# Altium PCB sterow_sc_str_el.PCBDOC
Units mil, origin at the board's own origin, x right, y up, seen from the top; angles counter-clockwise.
Board outline 6010 x 6345 mil, 2 copper layers (Top Layer, Bottom Layer); 70 components, 89 nets, 354 pads, 50 vias.
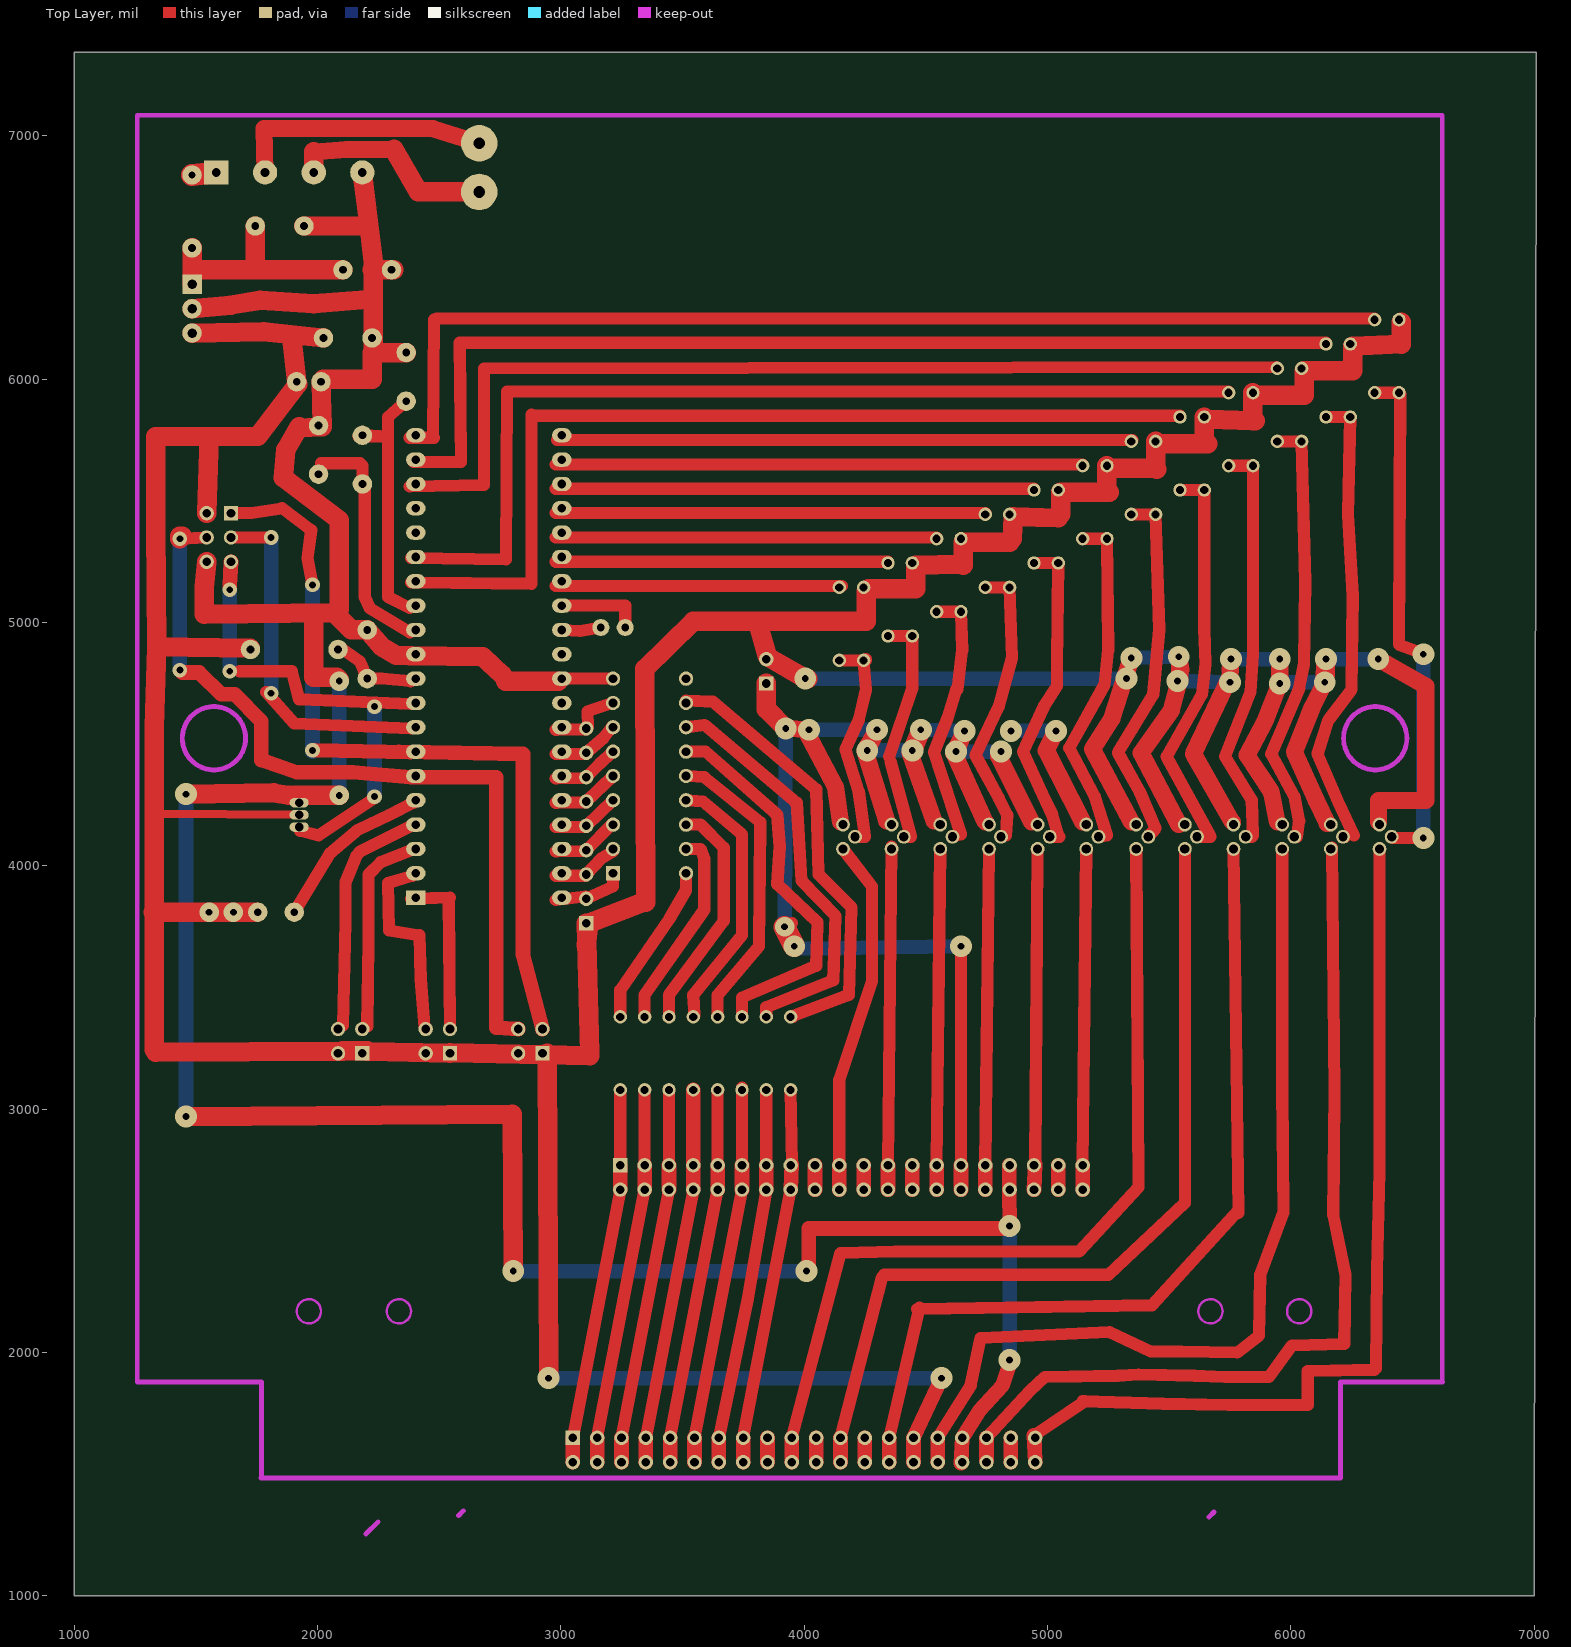
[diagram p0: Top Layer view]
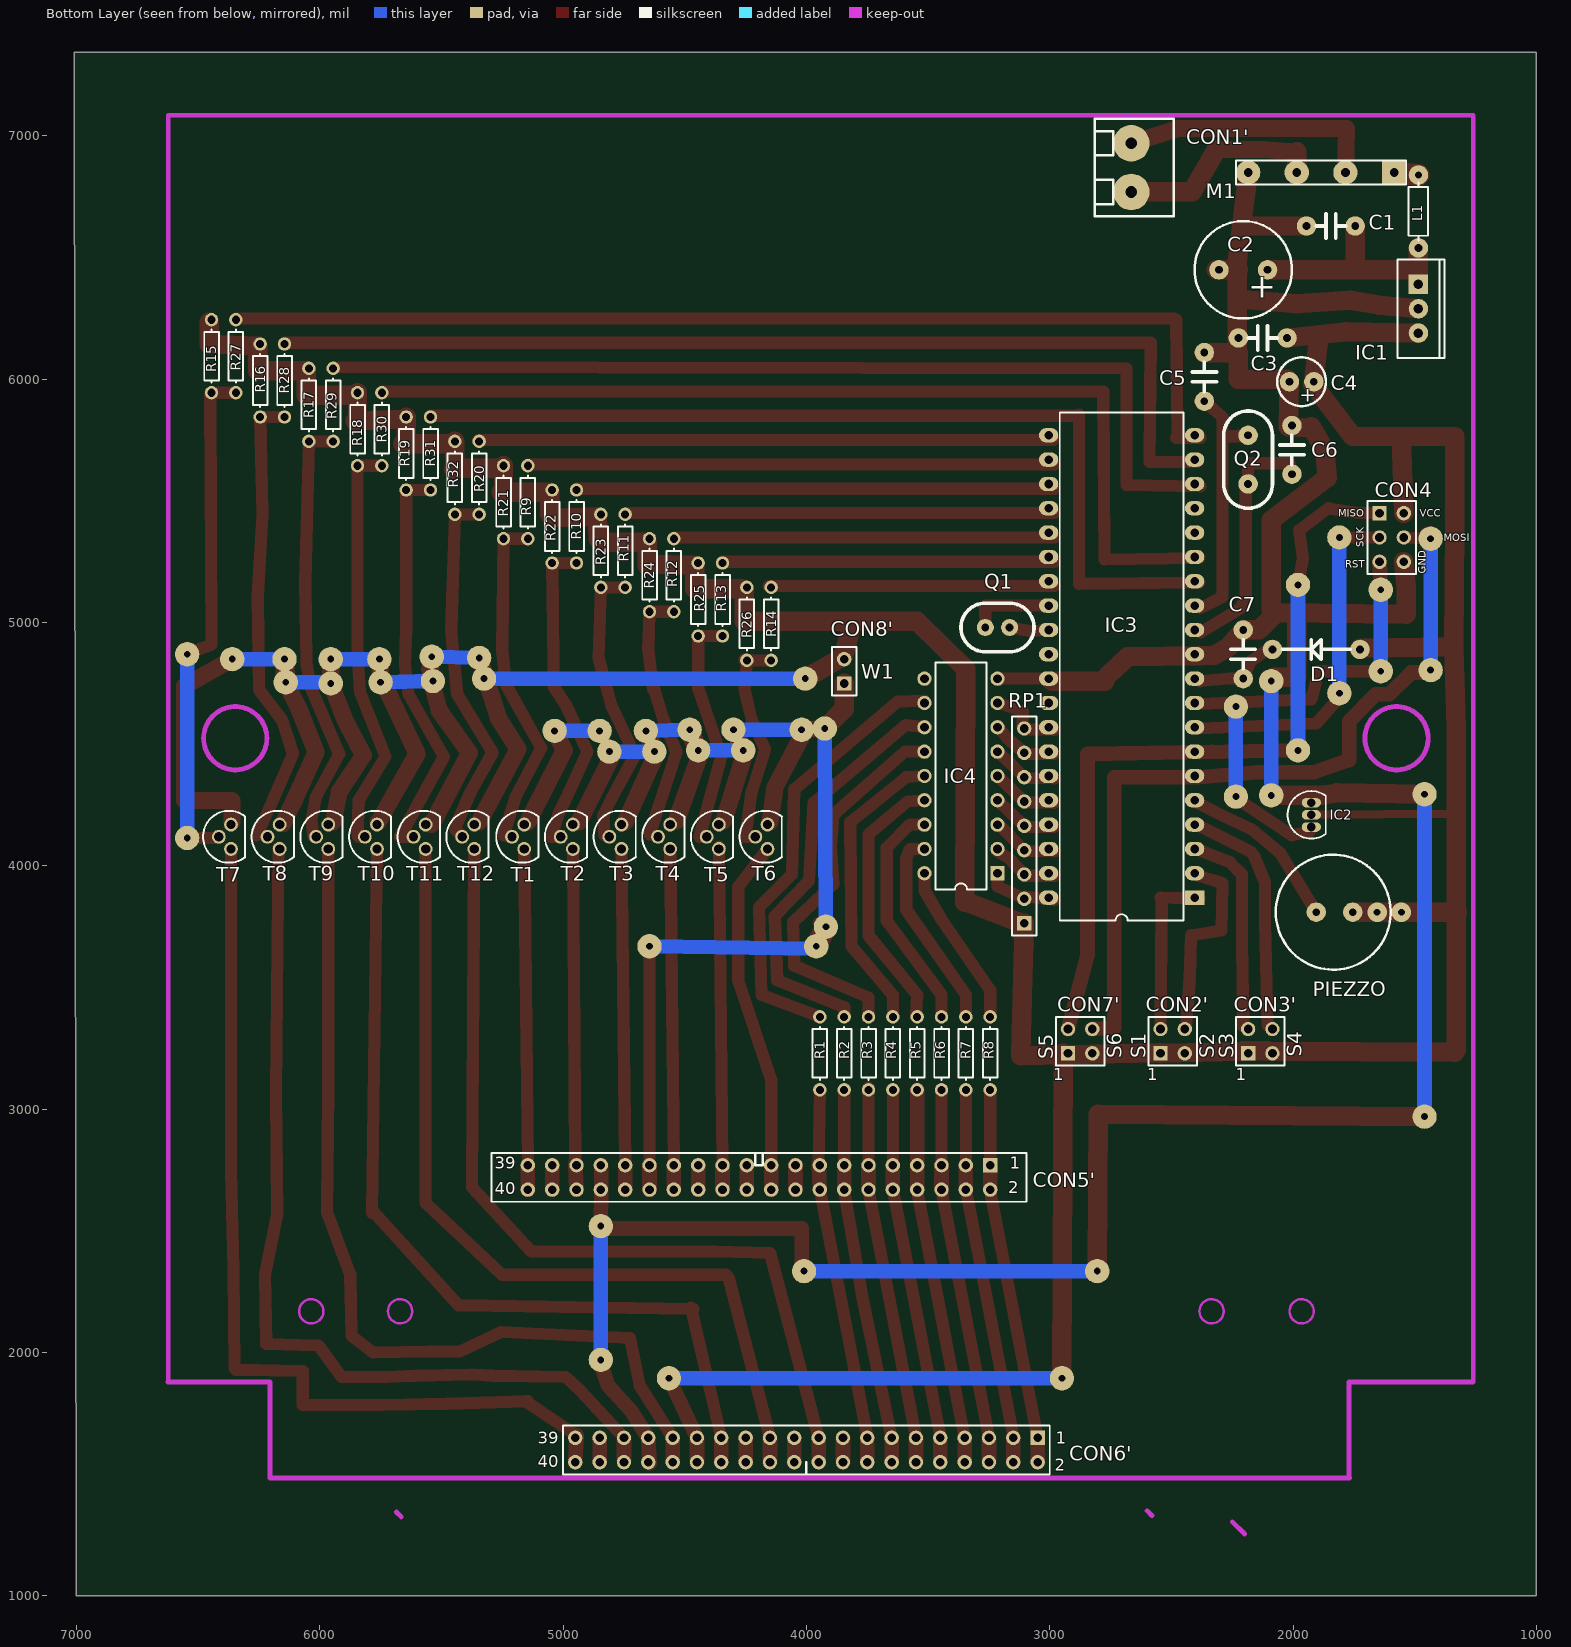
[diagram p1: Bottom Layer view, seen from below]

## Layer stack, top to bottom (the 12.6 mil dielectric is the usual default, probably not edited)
Top Layer: signal copper 1.4
Dielectric: dielectric 12.6, FR-4, Dk 4.8
Bottom Layer: signal copper 1.4

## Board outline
1000,1000 7000,1000 7010,7345 1000,7345

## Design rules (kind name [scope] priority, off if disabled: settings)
Clearance [All] p1: gap=10
ComponentClearance [All] p1: gap=1 collisioncheckmode=0
PolygonConnect [All] p1: connectstyle=Relief reliefconductorwidth=10 reliefentries=4 polygonreliefangle="90 Angle"
RoutingLayers [All] p1: top layer=Horizontal bottom layer=Vertical
RoutingVias [All] p1: holewidth=28 width=50 viastyle="Through Hole" minholewidth=28 minwidth=50 maxholewidth=28 maxwidth=50
SolderMaskExpansion [All] p1: expansion=4
TestPointUsage [All] p1: valid=0 allowmultiple=FALSE
Testpoint [All] p1: side=15 testpointundercomponent=TRUE minsize=40 maxsize=100 preferedsize=60 minholesize=0 maxholesize=40 preferedholesize=32 testpointgrid=1 style=1023 order=1234567890
Width [All] p1: maxlimit=90 minlimit=10 preferedwidth=10 toplayer_prefwidth=50 bottomlayer_prefwidth=80 minimp=50.000000 maximp=50.000000 favimp=50.000000
16 further rules are at their usual default settings.

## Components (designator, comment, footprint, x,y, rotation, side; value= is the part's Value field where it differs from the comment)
C1 "100nF" C2 1845,6630 r180 bottom
C2 "1000uF" CE10 2205,6450 r0 bottom
C3 "100nF" C2 2125,6170 r180 bottom
C4 "100uF" CE5 1965,5990 r0 bottom
C5 "27p" C2 2365,6010 r270 bottom
C6 "27p" C2 2005,5710 r270 bottom
C7 "100nF" C2 2205,4870 r270 bottom
CON1' "" ARK2 2665,6870 r90 bottom
CON2' "" HDR2X2 2545,3230 r180 bottom
CON3' "" HDR2X2 2185,3230 r180 bottom
CON4 "ISP" "HDR2X3_CEN - DUPLICATE" 1645,5450 r270 bottom
CON5' "Header 20X2" HDR2X20 3245,2770 r0 bottom
CON6' "Header 20X2" HDR2X20 3050,1650 r0 bottom
CON7' "" HDR2X2 2925,3230 r180 bottom
CON8' "Header 2" HDR1X2 3845,4750 r90 bottom
D1 "1N4148" D4 1905,4890 r0 bottom
IC1 "7805" 221A-04 1485,6290 r270 bottom
IC2 "DS1813" TO-92 1925,4210 r180 bottom
IC3 "ATmega8535" 40P6 2705,4820 r90 bottom
IC4 "ULN2803" DIP-18 3365,4370 r90 bottom
L1 "22uH" AXIAL-0.3#1 1485,6690 r90 bottom
M1 "Bridge1" HDR1X7 1585,6850 r0 bottom
PIEZZO "" PIEZO 1905,3810 r180 bottom (schematic designator Q3)
Q1 "32768Hz" X1 3265,4980 r0 bottom
Q2 "8MHz" X2 2185,5670 r90 bottom
R1 "Res2" AXIAL-0.3#2 3945,3230 r90 bottom
R2 "Res2" AXIAL-0.3#2 3845,3230 r90 bottom
R3 "Res2" AXIAL-0.3#2 3745,3230 r90 bottom
R4 "Res2" AXIAL-0.3#2 3645,3230 r90 bottom
R5 "Res2" AXIAL-0.3#2 3545,3230 r90 bottom
R6 "Res2" AXIAL-0.3#2 3445,3230 r90 bottom
R7 "Res2" AXIAL-0.3#2 3345,3230 r90 bottom
R8 "Res2" AXIAL-0.3#2 3245,3230 r90 bottom
R9 "Res2" AXIAL-0.3#2 5145,5495 r270 bottom
R10 "Res2" AXIAL-0.3#2 4945,5395 r270 bottom
R11 "Res2" AXIAL-0.3#2 4745,5295 r270 bottom
R12 "Res2" AXIAL-0.3#2 4545,5195 r270 bottom
R13 "Res2" AXIAL-0.3#2 4345,5095 r270 bottom
R14 "Res2" AXIAL-0.3#2 4145,4995 r270 bottom
R15 "3,3K" AXIAL-0.3#2 6445,6095 r90 bottom
R16 "3,3K" AXIAL-0.3#2 6245,5995 r90 bottom
R17 "3,3K" AXIAL-0.3#2 6045,5895 r90 bottom
R18 "3,3K" AXIAL-0.3#2 5845,5795 r90 bottom
R19 "3,3K" AXIAL-0.3#3 5645,5695 r90 bottom
R20 "3,3k" AXIAL-0.3#2 5345,5595 r270 bottom
R21 "Res2" AXIAL-0.3#2 5245,5495 r90 bottom
R22 "Res2" AXIAL-0.3#2 5045,5395 r90 bottom
R23 "Res2" AXIAL-0.3#2 4845,5295 r90 bottom
R24 "Res2" AXIAL-0.3#2 4645,5195 r90 bottom
R25 "Res2" AXIAL-0.3#2 4445,5095 r90 bottom
R26 "Res2" AXIAL-0.3#2 4245,4995 r90 bottom
R27 "3,3K" AXIAL-0.3#2 6345,6095 r270 bottom
R28 "3,3K" AXIAL-0.3#2 6145,5995 r270 bottom
R29 "3,3K" AXIAL-0.3#2 5945,5895 r270 bottom
R30 "3,3K" AXIAL-0.3#2 5745,5795 r270 bottom
R31 "3,3K" AXIAL-0.3#2 5545,5695 r270 bottom
R32 "3,3K" AXIAL-0.3#2 5445,5595 r90 bottom
RP1 "8x10K" HDR1X9 3105,3765 r90 bottom
T1 "BC557" TO92 5160,4070 r0 bottom
T2 "BC557" TO92 4960,4070 r0 bottom
T3 "*" TO92 4760,4070 r0 bottom
T4 "BC557" TO92 4560,4070 r0 bottom
T5 "BC557" TO92 4360,4070 r0 bottom
T6 "BC557" TO92 4160,4070 r0 bottom
T7 "BC557" TO92 6365,4070 r0 bottom
T8 "BC557" TO92 6165,4070 r0 bottom
T9 "BC557" TO92 5965,4070 r0 bottom
T10 "BC557" TO92 5765,4070 r0 bottom
T11 "BC557" TO92 5565,4070 r0 bottom
T12 "BC557" TO92 5365,4070 r0 bottom

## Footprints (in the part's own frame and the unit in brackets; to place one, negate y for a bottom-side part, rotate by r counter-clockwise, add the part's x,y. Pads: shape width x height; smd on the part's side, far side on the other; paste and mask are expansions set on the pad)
40P6 [mm]
  rect 1.5x2.032 hole 0.9: 1(-24.13,-7.62)
  oval 1.5x2.032 hole 0.9: 2(-21.59,-7.62) 3(-19.05,-7.62) 4(-16.51,-7.62) 5(-13.97,-7.62) 6(-11.43,-7.62) 7(-8.89,-7.62) 8(-6.35,-7.62) 9(-3.81,-7.62) 10(-1.27,-7.62) 11(1.27,-7.62) 12(3.81,-7.62) 13(6.35,-7.62) 14(8.89,-7.62) 15(11.43,-7.62) 16(13.97,-7.62) 17(16.51,-7.62) 18(19.05,-7.62) 19(21.59,-7.62) 20(24.13,-7.62) 21(24.13,7.62) 22(21.59,7.62) 23(19.05,7.62) 24(16.51,7.62) 25(13.97,7.62) 26(11.43,7.62) 27(8.89,7.62) 28(6.35,7.62) 29(3.81,7.62) 30(1.27,7.62) 31(-1.27,7.62) 32(-3.81,7.62) 33(-6.35,7.62) 34(-8.89,7.62) 35(-11.43,7.62) 36(-13.97,7.62) 37(-16.51,7.62) 38(-19.05,7.62) 39(-21.59,7.62) 40(-24.13,7.62)
  silkscreen extent -26.5,-6.45 26.5,6.45
221A-04 [mil]
  rect 80x80 hole 39.37: 1(-100,0)
  round 80 hole 39.37: 2(0,0) 3(100,0)
  silkscreen extent -203,-87 203,106
ARK2 [mil]
  round 150 hole 48: 1(-100,0) 2(100,0)
  silkscreen extent -200,-175 200,150
AXIAL-0.3#1 [mil]
  round 80 hole 33.47: 1(-150,0)
  round 80 hole 28: 2(150,0)
  silkscreen extent -120,-40 120,40
AXIAL-0.3#2 [mil]
  round 55.12 hole 33.46: 1(-150,0) 2(150,0)
  silkscreen extent -109,-30 109,30
AXIAL-0.3#3 [mil]
  round 55.12 hole 33.46: 1(-150,0)
  round 55.12 hole 33.47: 2(150,0)
  silkscreen extent -109,-30 109,30
C2 [mil]
  round 80 hole 32: 1(-100,0) 2(100,0)
  silkscreen extent -60,-50 60,50
CE5 [mil]
  round 80 hole 32: 1(-50,0) 2(50,0)
  silkscreen extent -100,-100 100,100
CE10 [mil]
  round 80 hole 32: 1(-100,0) 2(100,0)
  silkscreen extent -200,-200 200,200
D4 [mil]
  round 80 hole 32: 1(-180,0) 2(180,0)
  silkscreen extent -140,-40 140,40
DIP-18 [mm]
  rect 1.5x1.5 hole 0.9: 1(-10.16,-3.81)
  round 1.5 hole 0.9: 2(-7.62,-3.81) 3(-5.08,-3.81) 4(-2.54,-3.81) 5(0,-3.81) 6(2.54,-3.81) 7(5.08,-3.81) 8(7.62,-3.81) 9(10.16,-3.81) 10(10.16,3.81) 11(7.62,3.81) 12(5.08,3.81) 13(2.54,3.81) 14(0,3.81) 15(-2.54,3.81) 16(-5.08,3.81) 17(-7.62,3.81) 18(-10.16,3.81)
  silkscreen extent -11.85,-2.65 11.85,2.65
HDR1X2 [mm]
  rect 1.5x1.5 hole 0.9: 1(0,0)
  round 1.5 hole 0.9: 2(2.54,0)
  silkscreen extent -1.27,-1.27 3.81,1.27
HDR1X7 [mm]
  rect 2.54x2.54 hole 0.9: 1(0,0)
  round 2.54 hole 0.9: 2(5.08,0) 3(10.16,0) 4(15.24,0)
  silkscreen extent -1.27,-1.27 16.51,1.27
HDR1X9 [mm]
  rect 1.5x1.5 hole 0.9: 1(0,0)
  round 1.5 hole 0.9: 2(2.54,0) 3(5.08,0) 4(7.62,0) 5(10.16,0) 6(12.7,0) 7(15.24,0) 8(17.78,0) 9(20.32,0)
  silkscreen extent -1.27,-1.27 21.59,1.27
HDR2X2 [mm]
  rect 1.5x1.5 hole 0.9: 1(0,0)
  round 1.5 hole 0.9: 2(0,2.54) 3(2.54,0) 4(2.54,2.54)
  silkscreen extent -1.27,-1.27 3.81,3.81
"HDR2X3_CEN - DUPLICATE" [mm]
  rect 1.5x1.5 hole 0.9: 1(0,0)
  round 1.5 hole 0.9: 2(2.54,0) 3(5.08,0) 4(5.08,2.54) 5(2.54,2.54) 6(0,2.54)
  silkscreen extent -1.27,-1.27 6.35,3.81
HDR2X20 [mm]
  rect 1.5x1.5 hole 0.9: 1(0,0)
  round 1.5 hole 0.9: 2(0,2.54) 3(2.54,0) 4(2.54,2.54) 5(5.08,0) 6(5.08,2.54) 7(7.62,0) 8(7.62,2.54) 9(10.16,0) 10(10.16,2.54) 11(12.7,0) 12(12.7,2.54) 13(15.24,0) 14(15.24,2.54) 15(17.78,0) 16(17.78,2.54) 17(20.32,0) 18(20.32,2.54) 19(22.86,0) 20(22.86,2.54) 21(25.4,0) 22(25.4,2.54) 23(27.94,0) 24(27.94,2.54) 25(30.48,0) 26(30.48,2.54) 27(33.02,0) 28(33.02,2.54) 29(35.56,0) 30(35.56,2.54) 31(38.1,0) 32(38.1,2.54) 33(40.64,0) 34(40.64,2.54) 35(43.18,0) 36(43.18,2.54) 37(45.72,0) 38(45.72,2.54) 39(48.26,0) 40(48.26,2.54)
  silkscreen extent -3.81,-1.27 52.07,3.81
PIEZO [mil]
  round 80 hole 32: 1(0,0) 2(150,0)
  silkscreen extent -166,-236 306,236
TO92 [mil]
  round 57 hole 38: 1(0,0) 2(50,-50) 3(0,-100)
  silkscreen extent -59,-157 115,57
TO-92 [mm]
  oval 2x1 hole 0.9: 1(0,-1.27) 2(0,0) 3(0,1.27)
  silkscreen extent -2.48,-2.48 1.5,2.48
X1 [mil]
  round 70 hole 32: 1(0,0) 2(-100,0)
  silkscreen extent -200,-100 100,100
X2 [mil]
  round 80 hole 32: 1(100,0) 2(-100,0)
  silkscreen extent -200,-100 200,100

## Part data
C1 C3 C5 C6 C7: library part C, "Kondensator"
C2 C4: library part EL, "Elektrolit"
CON1': library part "Header 2", "Header, 2-Pin"
CON2' CON3' CON7': library part "Header 2X2", "Header, 2-Pin, Dual row"
CON4: library part "Header 3X2_ISP", "Header, 3-Pin, Dual row"
CON5': "Header, 20-Pin, Dual row"
CON6': library part "Edge Con 22", "22-Pin Edge Connector"
CON8': "Header, 2-Pin"
D1: library part D, "Dioda"
IC1: library part MC7805ACT, "3-Terminal Positive Fixed Voltage Regulator"
IC2: library part DS1813-10, "5V EconoReset with Pushbutton"
IC3: library part ATmega8535-16PU, "8-Bit AVR Microcontroller with 8K Bytes of In-System Programmable Flash Memory"
IC4: library part ULN2803A, "Octal Peripheral Driver Array"
M1: "Full Wave Diode Bridge"
PIEZZO: library part PIEZO, "Loudspeaker"
Q1 Q2: library part CRYSTAL_1, "rezonator"
R1 R2 R3 R4 R5 R6 R7 R8 R9 R10 R11 R12 R13 R14 R21 R22 R23 R24 R25 R26: "Resistor"
R15 R16 R17 R18 R19 R20 R27 R28 R29 R30 R31 R32: library part Res2, "Resistor"
RP1: library part "Res Pack4", "Resistor Array"
T1 T2 T4 T5 T6 T7 T8 T9 T10 T11 T12: "Amplifier Transistor PNP Silicon"
T3: library part BC557, "Amplifier Transistor PNP Silicon"

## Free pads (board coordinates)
  round 30 on Keep-Out: 0(2885,1335)
  round 100 smd far side: 0(6545,4115) 1(6545,4870) 3(1980,5155) 4(1980,4475) 4(2805,2335) 4(3925,4565) 4(4020,4560) 4(4645,3670) 5(2235,4655) 5(3960,3670) 6(2235,4285) 7(2090,4760) 8(2090,4290) 9(2950,1895) 9(4845,2520) 10(3920,3750) 10(6360,4850) 11(6145,4850) 12(6140,4755) 13(5955,4750) 14(5955,4850) 15(4565,1895) 15(5750,4755) 16(4845,1970) 16(5755,4850) 17(5535,4760) 18(5540,4860) 19(5325,4770) 20(5345,4855) 21(4005,4770) 22(4810,4470) 23(4625,4470) 24(4445,4475) 25(4480,4560) 26(4660,4555) 27(1640,4800) 27(4850,4555) 28(1640,5135) 28(5035,4555) 29(1810,4710) 29(4260,4475) 30(1810,5350) 30(4300,4560) 31(1435,5345) 32(1435,4805) 35(1460,4295) 36(1460,4295) 37(1460,2970) 38(1460,2970) 41(4010,2335)

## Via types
v1: diameter 90, hole 28, Top Layer to Bottom Layer, 35 vias
v2: diameter 60, hole 28, Top Layer to Bottom Layer, 10 vias
v3: diameter 80, hole 28, Top Layer to Bottom Layer, 5 vias

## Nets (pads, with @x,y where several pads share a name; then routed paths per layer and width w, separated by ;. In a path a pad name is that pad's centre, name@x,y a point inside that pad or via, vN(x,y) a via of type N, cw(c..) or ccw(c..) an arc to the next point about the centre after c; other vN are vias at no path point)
A1': CON5'.39 CON5'.40 T1.1 | length 1400.1
  Top Layer w50: CON5'.39 T1.1
  Top Layer w60: CON5'.40 CON5'.39
A2': CON5'.35 CON5'.36 T2.1 | length 1400.2
  Top Layer w50: CON5'.35@4950,2775 T2.1
  Top Layer w60: CON5'.36 CON5'.35@4950,2775
A3': CON5'.31 CON5'.32 T3.1 | length 1400.1
  Top Layer w50: CON5'.31 T3.1
  Top Layer w60: CON5'.32 CON5'.31
A4': CON5'.27 CON5'.28 T4.1 | length 1400.1
  Top Layer w50: CON5'.27 T4.1
  Top Layer w60: CON5'.28 CON5'.27
A5': CON5'.23 CON5'.24 T5.1 | length 1410.1
  Top Layer w50: CON5'.23 T5.1@4360,4080
  Top Layer w60: CON5'.24 CON5'.23
A6': CON5'.19 CON5'.20 T6.1 | length 1462.7
  Top Layer w50: CON5'.19 4145,3120 4280,3530 4280,3915 T6.1
  Top Layer w60: CON5'.20 CON5'.19
A7': CON6'.39 CON6'.40 T7.1 | length 3837.9
  Top Layer w50: CON6'.39@4945,1660 5155,1800 ; 5145,1800 5475,1790 5745,1785 6070,1785 6070,1925 6345,1930 ; 6350,1935 6355,2340 6365,2745 6365,3535 T7.1
  Top Layer w60: CON6'.39@4945,1660 CON6'.40
A8': CON6'.35 CON6'.36 T8.1 | length 3778.4
  Top Layer w50: CON6'.35 4930,1845 4990,1900 5290,1905 5375,1910 5605,1905 5730,1900 5910,1900 6005,2030 6220,2035 6225,2320 6175,2565 6180,3070 T8.1@6170,4075
  Top Layer w60: CON6'.36@4750,1560 CON6'.35
A9': CON6'.31 CON6'.32 T9.1 | length 3757.7
  Top Layer w50: CON6'.31 4685,1865 4725,2060 5255,2085 5425,2005 5550,2005 5780,2000 5870,2070 5875,2320 5970,2575 5965,3080 T9.1
  Top Layer w60: CON6'.32 CON6'.31
A10': CON6'.27 CON6'.28 T10.1 | length 3637
  Top Layer w50: CON6'.27 4475,2185 ; 4465,2180 5430,2195 5785,2585 ; T10.1 5785,2575
  Top Layer w60: CON6'.28 CON6'.27
A11': CON6'.23 CON6'.24 T11.1 | length 3568.1
  Top Layer w50: CON6'.23 4320,2310 ; 4330,2320 5250,2320 5565,2615 ; 5565,2620 T11.1@5565,4055
  Top Layer w60: CON6'.24 CON6'.23
A12': CON6'.19 CON6'.20 T12.1 | length 3611.9
  Top Layer w50: CON6'.19 4150,2410 4375,2415 5130,2415 5375,2680 ; T12.1 5375,2685
  Top Layer w60: CON6'.20 CON6'.19
A': CON5'.15 CON5'.16 CON6'.15 CON6'.16 R1.1 | length 1548.6
  Top Layer w50: CON6'.15 CON5'.16 ; R1.1 CON5'.15@3950,2775
  Top Layer w60: CON6'.16 CON6'.15 ; CON5'.16 CON5'.15@3950,2775
B': CON5'.13 CON5'.14 CON6'.13 CON6'.14 R2.1 | length 1548.7
  Top Layer w50: CON6'.13 3770,2225 CON5'.14 ; CON5'.13 R2.1
  Top Layer w60: CON6'.14 CON6'.13 ; CON5'.14 CON5'.13
C1: IC3.22 R9.1 | length 2165
  Top Layer w50: IC3.22@2980,5650 R9.1@5145,5650
C2: IC3.23 R10.1 | length 1965
  Top Layer w50: IC3.23@2980,5550 R10.1@4945,5550
C3: IC3.24 R11.1 | length 1765
  Top Layer w50: IC3.24@2980,5450 R11.1@4745,5450
C4: IC3.25 R12.1 | length 1565
  Top Layer w50: IC3.25@2980,5350 R12.1@4545,5350
C5: IC3.26 R13.1 | length 1365
  Top Layer w50: IC3.26@2980,5250 R13.1@4345,5250
C6: IC3.27 R14.1 | length 1175
  Top Layer w50: IC3.27@2980,5150 R14.1@4155,5150
C7: IC3.20 R27.1 | length 4440
  Top Layer w50: IC3.20@2380,5760 2480,5760 ; 2475,5760 2480,6245 ; 2490,6250 R27.1@6345,6250
C8: IC3.19 R28.1 | length 4235
  Top Layer w50: IC3.19@2395,5660 2580,5660 ; 2590,5660 2585,6150 R28.1@6145,6150
C9: IC3.18 R29.1 | length 4047.1
  Top Layer w50: IC3.18@2380,5560 2685,5565 2685,6045 5940,6050 R29.1
C10: IC3.15 R30.1 | length 4045.1
  Top Layer w50: IC3.15@2385,5265 2775,5260 2780,5950 R30.1@5745,5950
C11: IC3.14 R31.1 | length 3855
  Top Layer w50: IC3.14@2385,5165 2880,5160 2880,5855 ; 2880,5850 R31.1@5545,5850
C12: IC3.21 R20.1 | length 2365
  Top Layer w50: IC3.21@2985,5750 R20.1@5350,5750
C': CON5'.11 CON5'.12 CON6'.11 CON6'.12 R3.1 | length 1558.5
  Top Layer w50: CON6'.11 CON5'.12 ; CON5'.11 R3.1@3745,3090
  Top Layer w60: CON6'.12 CON6'.11 ; CON5'.12 CON5'.11
D': CON5'.9 CON5'.10 CON6'.9 CON6'.10 R4.1 | length 1548.5
  Top Layer w50: CON6'.9 CON5'.10 ; CON5'.9 R4.1
  Top Layer w60: CON6'.10 CON6'.9 ; CON5'.10 CON5'.9
DP': CON5'.1 CON5'.2 CON6'.1 CON6'.2 R8.1 | length 1548.5
  Top Layer w50: CON6'.1 CON5'.2 ; CON5'.1 R8.1
  Top Layer w60: CON6'.2 CON6'.1 ; CON5'.2 CON5'.1
E': CON5'.7 CON5'.8 CON6'.7 CON6'.8 R5.1 | length 1548.5
  Top Layer w50: CON6'.7 CON5'.8
  Top Layer w60: CON6'.8 CON6'.7 ; CON5'.8 R5.1
F': CON5'.5 CON5'.6 CON6'.5 CON6'.6 R6.1 | length 1548.5
  Top Layer w50: CON6'.5 CON5'.6 ; CON5'.5 R6.1
  Top Layer w60: CON6'.6 CON6'.5 ; CON5'.6 CON5'.5
G': CON5'.3 CON5'.4 CON6'.3 CON6'.4 R7.1 | length 1548.5
  Top Layer w50: CON6'.3 CON5'.4 ; CON5'.3 R7.1
  Top Layer w60: CON6'.4 CON6'.3 ; CON5'.4 CON5'.3
GND': C1.1 C2.2 C3.1 C4.2 C5.1 C6.1 C7.1 CON4.4 CON5'.33 CON5'.34 CON6'.33 CON6'.34 IC1.2 IC2.3 IC3.11 IC3.31 IC4.9 M1.4 pad.4@2805,2335 pad.7 pad.8 pad.9@4845,2520 pad.16@4845,1970 pad.35 pad.36 pad.37 pad.38 pad.41 | length 13655.8
  Top Layer w50: C4.2 C4.2@2025,6000 ; IC3.31@2990,4770 IC4.9
  Top Layer w60: v1@4020,2340 4020,2510 v1@4845,2510 ; CON6'.34@4645,1545 CON6'.33 4720,1760 4815,1865 v1@4850,1970 ; CON5'.33@4842.83,2769.98 4843.7,2669.99 v1(4845,2520)
  Top Layer w80: v1(1460,2970) 2800,2980 v1@2805,2345 ; v1(1460,4295) 1820,4300 1885,4290 ; IC1.2 1645,6305 1765,6325 1985,6310 2230,6330 ; CON4.4 1535,5145 1535,5035 2070,5040 2140,4970 C7.1 2265,4900 2325,4865 IC3.11@2380.06,4864.22 ; 1905,4290 v3(2090,4290) ; 1925,5805 1870,5710 1860,5595 2090,5420 2090,5055 ; 1930,5800 2020,5805 2019.85,5810.4 C4.2 ; C1.1 2212.12,6630 ; 1985,5005 1985,4775 2080,4775 v3@2090,4765 ; C4.2@2025,6000 2225,6000 2225,6110 C5.1 ; M1.4 2212.12,6630 ; 2225,6450 C2.2@2315,6450 ; 2230,6105 2230,6485 2212.12,6630 ; IC3.11@2384.99,4864.16 2680,4860 2760,4785 ; 2775,4760 IC3.31@2990,4760
  Bottom Layer w60: v1(1460,2970) v1(1460,4295) ; v3(2090,4290) v3(2090,4760) ; v1(2805,2335) v1(4010,2335) ; v1(4845,1970) v1(4845,2520)
MISO: CON4.1 CON7'.2 IC3.7 pad.3 pad.4@1980,4475 | length 3325
  Top Layer w50: CON4.1 1730,5450 1855,5470 1975,5380 1960,5265 v2(1980,5155) ; IC3.7@2381.23,4466.62 2385.17,4465.9 IC3.7@2390,4465
  Top Layer w60: v2@1990,4475 IC3.7@2381.23,4466.62 ; 2335,4470 2845,4460 2845,3635 CON7'.2
  Bottom Layer w60: pad.4@1980,4470 v2(1980,5155)
  other v2: 1980,4475
MOSI: CON4.5 CON7'.4 IC3.6 pad.31 pad.32 | length 3336.4
  Top Layer w50: v2(1435,5345) CON4.5
  Top Layer w60: v2@1445,4795 1515,4795 1605,4705 1660,4705 1770,4595 1770,4435 1915,4385 2145,4385 2385,4365 2735,4365 2735,3855 2735,3335 CON7'.4
  Top Layer w80: v2(1435,5345) 1445,5355 v2@1435,5355
  Bottom Layer w60: v2(1435,4805) v2(1435,5345)
NC1': CON5'.37 CON5'.38 | length 100
  Top Layer w60: CON5'.38 CON5'.37
NC2': CON5'.25 CON5'.26 | length 100
  Top Layer w60: CON5'.26 CON5'.25
NC3': CON5'.21 CON5'.22 | length 100
  Top Layer w60: CON5'.22 CON5'.21
NC4': CON5'.17 CON5'.18 | length 100
  Top Layer w60: CON5'.18 CON5'.17
NC5': CON6'.37 CON6'.38 | length 100
  Top Layer w60: CON6'.38 CON6'.37
NC6': CON6'.25 CON6'.26 | length 100
  Top Layer w60: CON6'.26 CON6'.25
NC7': CON6'.21 CON6'.22 | length 100
  Top Layer w60: CON6'.22 CON6'.21
NC8': CON6'.17 CON6'.18 | length 100
  Top Layer w60: CON6'.18 CON6'.17
NetC1_2: C1.2 C2.1 IC1.1 L1.1 | length 945
  Top Layer w80: IC1.1 L1.1 ; 1485,6450 C2.1 ; 1745,6455 C1.2
NetCON1'_1: CON1'.1 M1.3 | length 866.9
  Top Layer w70: 1985,6935 2120,6945 2315,6945
  Top Layer w80: M1.3 1985,6935 ; 2315,6945 2415,6770 CON1'.1
NetCON1'_2: CON1'.2 M1.2 | length 1074.3
  Top Layer w70: M1.2 1780,7030 2475,7030 CON1'.2
NetIC4_11: IC4.11 R1.2 | length 1844.6
  Top Layer w50: IC4.11@3515,4680 3625,4675 4050,4315 4060,3965 4195,3830 4185,3470 R1.2 ; R1.2 3955,3380 R1.2
NetIC4_12: IC4.12 R2.2 | length 1696
  Top Layer w50: IC4.12 3590,4580 3970,4260 3990,3940 4130,3795 4120,3530 3845,3420 R2.2
NetIC4_13: IC4.13 R3.2 | length 1576.9
  Top Layer w50: IC4.13 3595,4470 3890,4210 3900,4080 3890,3925 4055,3770 4050,3590 3745,3460 R3.2
NetIC4_14: IC4.14 R4.2 | length 1207.9
  Top Layer w50: IC4.14@3525,4370 3590,4365 3820,4180 ; R4.2 3645,3470 3815,3670 3820,4165
NetIC4_15: IC4.15 R5.2 | length 1103
  Top Layer w50: IC4.15 3585,4265 3745,4130 3745,3715 3545,3470 3550,3385 R5.2
NetIC4_16: IC4.16 R6.2 | length 963.4
  Top Layer w50: R6.2 3445,3470 3670,3775 3670,4075 3575,4170 IC4.16
NetIC4_17: IC4.17 R7.2 | length 809.9
  Top Layer w50: R7.2@3345,3390 3345,3470 3590,3820 3590,4030 3575,4070 IC4.17@3525,4070
NetIC4_18: IC4.18 R8.2 | length 671.2
  Top Layer w50: R8.2 3245,3490 3445,3780 3515,3900 IC4.18
NetL1_2: L1.2 M1.1 | length 100.5
  Top Layer w90: L1.2 M1.1
NetR9_2: R9.2 R21.1 T1.2 | length 1427.4
  Top Layer w50: R9.2 R21.1 5250,4885 5235,4745 5090,4485 5195,4285 5245,4125 T1.2
NetR10_2: R10.2 R22.1 T2.2 | length 1324.8
  Top Layer w50: R10.2 R22.1 5040,4830 5040,4740 4985,4655 4900,4470 4980,4295 5020,4210 5045,4125 ; T2.2 5050,4120
NetR11_2: R11.2 R23.1 T3.2 | length 1181.5
  Top Layer w50: R11.2 R23.1 4855,4855 4800,4655 4705,4455 4800,4280 4835,4210 T3.2@4830,4125
NetR12_2: R12.2 R24.1 T4.2 | length 1080.9
  Top Layer w50: 4535,4465 4645,4130 T4.2 ; 4535,4470 4590,4610 4625,4725 ; R12.2 R24.1 4650,4885 4630,4725
NetR13_2: R13.2 R25.1 T5.2 | length 962.1
  Top Layer w50: R13.2 R25.1 4445,4730 4350,4450 ; 4355,4430 4440,4120 T5.2
NetR14_2: R14.2 R26.1 T6.2 | length 876.3
  Top Layer w50: R14.2@4165,4845 R26.1 4255,4725 4225,4600 4170,4480 4225,4305 4250,4120.28 4250,4120 T6.2 ; R26.1@4254.91,4844.82 R26.1@4255,4850
NetR15_1: pad.0@6545,4115 pad.1 R15.1 R27.2 T7.2 | length 2132.5
  Top Layer w50: R27.2 R15.1 6450,5940 6445,4910 6540,4875 v1(6545,4870) ; T7.2 6420,4115 v1(6545,4115)
  Bottom Layer w60: v1(6545,4115) v1(6545,4870)
NetR16_1: R16.1 R28.2 T8.2 | length 1899
  Top Layer w50: R28.2 R16.1 6235,5445 6255,5110 6250,4725 6155,4600 6110,4460 6195,4265 6260,4125 ; T8.2 T8.2@6222.08,4120
NetR17_1: R17.1 R29.2 T9.2 | length 1787.6
  Top Layer w50: R29.2 R17.1 6060,5165 6055,4830 6035,4730 5920,4460 6015,4285 6035,4185 6025,4120 T9.2
NetR18_1: R18.1 R30.2 T10.2 | length 1703.5
  Top Layer w50: R30.2 R18.1 5845,4975 5845,4870 5835,4715 5730,4450 5840,4270 5845,4125 5840,4120 T10.2
NetR19_1: R19.1 R31.2 T11.2 | length 1665.2
  Top Layer w50: R31.2 R19.1 5645,4975 5650,4830 5635,4705 5490,4450 5670,4120 T11.2
NetR20_2: R20.2 R32.1 T12.2 | length 1515
  Top Layer w50: R20.2 R32.1 5460,4970 5435,4705 5290,4465 5380,4305 5445,4155 T12.2
OSC1: IC3.28 Q1.1 | length 350
  Top Layer w50: IC3.28 3265,5070 Q1.1
OSC2: IC3.29 Q1.2 | length 161.5
  Top Layer w50: IC3.29 3080,4965 Q1.2
PA0: IC3.40 IC4.1 RP1.2 | length 301.4
  Top Layer w50: IC3.40@2980,3860 3100,3875 3115,3870 3215,3915 IC4.1
PA1: IC3.39 IC4.2 RP1.3 | length 283.8
  Top Layer w50: IC3.39@2980,3960 3100,3960 RP1.3 3165,4030 3215,4060 IC4.2
PA2: IC3.38 IC4.3 RP1.4 | length 278.5
  Top Layer w50: IC3.38@2980,4060 2985.05,4060.05 RP1.4@3105.04,4061.34 ; RP1.4 3210,4170 IC4.3
PA3: IC3.37 IC4.4 RP1.5 | length 277.1
  Top Layer w50: IC3.37@2980,4160 2985.04,4160.04 RP1.5@3105.03,4161.11 ; RP1.5 IC4.4
PA4: IC3.36 IC4.5 RP1.6 | length 277.1
  Top Layer w50: IC3.36@2980,4260 2985.04,4260.04 RP1.6@3105.03,4260.94 ; RP1.6 IC4.5
PA5: IC3.35 IC4.6 RP1.7 | length 277.2
  Top Layer w50: IC3.35@2980,4360 2985.06,4360.07 RP1.7@3105.04,4361.63 ; RP1.7 3160,4420 IC4.6
PA6: IC3.34 IC4.7 RP1.8 | length 274.2
  Top Layer w50: IC3.34@2980,4460 2985.03,4460.03 RP1.8@3105.02,4460.72 ; RP1.8 3175,4525 IC4.7@3210,4570
PA7: IC3.33 IC4.8 RP1.9 | length 298.5
  Top Layer w50: IC3.33@2980,4560 2985.03,4560.03 RP1.9@3105.02,4560.65 ; RP1.9@3112.24,4572.24 3110,4635 IC4.8
PIEZO: IC3.5 PIEZZO.1 | length 687.1
  Top Layer w50: PIEZZO.1 2050,4050 2170,4150 2295,4210 IC3.5@2395,4260
RST: CON4.3 IC2.1 IC3.9 pad.5@2235,4655 pad.6 pad.27@1640,4800 pad.28@1640,5135 | length 1954.4
  Top Layer w50: 1680,4800 1895,4800 1925,4685 IC3.9@2385,4665 ; IC2.1@1930,4145 2005,4125 v2@2235,4280
  Top Layer w60: v2@1640,5150 CON4.3
  Bottom Layer w60: v2(1640,4800) v2(1640,5135) ; v2(2235,4285) v2(2235,4655)
S1': CON2'.2 IC3.1 | length 702.2
  Top Layer w50: IC3.1@2385,3865 2545,3870 2540,3865 CON2'.2
S2': CON2'.4 IC3.2 | length 801.7
  Top Layer w50: IC3.2@2390,3960 2290,3930 2295,3735 2420,3715 2425,3535 CON2'.4@2440,3340
S3': CON3'.2 IC3.3 | length 830.4
  Top Layer w50: CON3'.2@2205,3340 2210,3690 2210,3965 2260,4015 IC3.3@2385,4065
S4': CON3'.4 IC3.4 | length 963.8
  Top Layer w50: CON3'.4@2105,3345 2115,3770 2115,3930 2160,4040 2175,4060 IC3.4@2385,4165
SCK: CON4.2 IC3.8 pad.29@1810,4710 pad.30@1810,5350 | length 1444
  Top Layer w50: CON4.2@1660,5350 v2(1810,5350) ; v2@1790,4715 1905,4585 IC3.8@2385,4565
  Bottom Layer w60: v2(1810,4710) v2(1810,5350)
VCC: CON5'.29 CON5'.30 CON8'.1 pad.4@3925,4565 pad.4@4020,4560 pad.4@4645,3670 pad.5@3960,3670 pad.10@3920,3750 pad.22 pad.23 pad.24 pad.25 pad.26 pad.27@4850,4555 pad.28@5035,4555 pad.29@4260,4475 pad.30@4300,4560 T1.3 T2.3 T3.3 T4.3 T5.3 T6.3 | length 6604.9
  Top Layer w50: v3(3920,3750) v3@3950,3765 ; CON5'.29 v1(4645,3670)
  Top Layer w60: CON5'.30 CON5'.29
  Top Layer w70: v1(3925,4565) v1(4020,4560) ; v1@4005,4560 4008.31,4553.78 4130,4325 T6.3@4150,4180 ; v1(4260,4475) v1(4300,4560) 4250,4475 T5.3@4340,4185 ; v1(4480,4560) 4435,4465 4535,4185 ; v1(4625,4470) v1(4660,4555) 4615,4465 T3.3@4745,4180 ; v1(4810,4470) 4800,4450 T2.3@4935,4180 ; v1(5035,4555) 4995,4475 T1.3@5145,4180
  Top Layer w80: CON8'.1 3845,4645 v1(3925,4565) ; v1(4445,4475) v1(4480,4560)
  Top Layer w90: v3(3920,3750) v1(3960,3670)
  Bottom Layer w60: v3(3920,3750) v1(3925,4565) ; pad.5@3960,3660 v1(4645,3670) ; v1(4020,4560) v1(4300,4560) ; v1(4260,4475) v1(4445,4475) ; v1(4480,4560) v1(4660,4555) ; v1(4625,4470) v1(4810,4470) ; v1(4850,4555) v1(5035,4555)
VCC': C3.2 C4.1 CON2'.1 CON2'.3 CON3'.1 CON3'.3 CON4.6 CON6'.29 CON6'.30 CON7'.1 CON7'.3 CON8'.2 D1.1 IC1.3 IC2.2 pad.9@2950,1895 pad.10@6360,4850 pad.11 pad.12 pad.13 pad.14 pad.15 pad.16@5755,4850 pad.17 pad.18 pad.19 pad.20 pad.21 PIEZZO.2 R15.2 R16.2 R17.2 R18.2 R19.2 R21.2 R22.2 R23.2 R24.2 R25.2 R26.2 R32.2 RP1.1 T7.3 T8.3 T9.3 T10.3 T11.3 T12.3 | length 24632.2
  Top Layer w35: 1330,4214.92 IC2.2
  Top Layer w50: R17.2@6050,6040 R17.2@6055,6035
  Top Layer w60: CON6'.30 CON6'.29 v1(4565,1895)
  Top Layer w70: v1(4005,4770) v1@4015,4770 ; T12.3@5345,4180 5185,4480 5265,4605 v1(5345,4855) ; T11.3@5540,4170 5385,4465 5510,4640 5545,4770 v1(5540,4860) 5550,4805 ; 5750,4805 v1(5755,4850) 5750,4775 5600,4460 T10.3@5760,4180 ; T9.3@5945,4180 5920,4305 5820,4455 5895,4595 v1(5955,4750) ; v1(6145,4850) v1(6140,4755) 6090,4655 6015,4470 6105,4270 T8.3@6150,4175 ; T7.3@6360,4180 6360,4270 6555,4270 6555,4740 v1(6360,4850) ; v1(5955,4750) v1(5955,4850) v1(5955,4750)
  Top Layer w80: 1325,3810 PIEZZO.2@1750,3810 ; 1330,3245 1330,4570 1340,4900 ; 1335,3235 CON3'.3@2105.13,3239.04 ; IC1.3 1780,6195 C3.2 ; CON4.6 1555,5765 ; D1.1@1725.07,4895.06 1340,4900 ; 1895,6170 C4.1 ; C4.1@1920,5980 1755,5765 1335,5765 1335,5395 1340,4900 ; CON3'.3@2105.02,3241.4 CON3'.1@2205,3240 ; CON3'.1@2205.11,3237.64 CON2'.1 ; CON2'.1@2545.04,3232.86 3120,3220 ; CON7'.1@2945,3230 v1(2950,1895) ; 3105,3675 3115,3765 3350,3855 ; RP1.1 3119.85,3230.55 ; 3345,4805 3350,3850 ; 3345,4810 3545,5005 4255,5005 ; 3810,5000 3850,4860 v1(4005,4770) v1@4015,4770 ; 4255,5015 R26.2@4255,5130 ; R26.2@4265,5140 4460,5140 4460,5235 4640,5240 ; 4655,5235 4655,5330 4845,5330 ; 4855,5345 4860,5435 5045,5430 ; 5055,5445 5055,5535 5255,5535 ; 5245,5535 R21.2 ; R21.2@5255,5635 5445,5635 ; R32.2 5445,5635 ; 5450,5630 5445,5635 ; R32.2@5455,5735 5660,5735 ; R19.2 5645,5740 5650,5735 ; R19.2@5660,5835 5845,5830.26 5855,5830 ; 5845,5830 R18.2 ; R18.2@5860,5935 6055,5935 6055,6035 6255,6035 6255,6135 6455,6145 R15.2@6455,6235 ; v1(6140,4755) v1(6145,4850)
  Bottom Layer w60: v1(2950,1895) v1(4565,1895) ; v1(4005,4770) v1(5325,4770) ; v1(5345,4855) v1(5540,4860) ; v1(5535,4760) v1(5750,4755) ; v1(5755,4850) v1(5955,4850) ; pad.13@5960,4755 v1(6140,4755) ; v1(6145,4850) v1(6360,4850)
  other v3: 1555,3810 1655,3810
VCP: C7.2 D1.2 IC3.10 | length 340.2
  Top Layer w50: D1.2@2105,4890 2175,4840 C7.2 2265,4770 2380,4760 IC3.10@2382.36,4758.97
X1: C5.2 IC3.13 Q2.1 | length 1145
  Top Layer w50: Q2.1@2170,5765 2270,5765 ; Q2.1 2195,5770 2290,5765 ; C5.2 2290,5845 2290,5765 ; IC3.13@2380,5060 2290,5105 2290,5765
X2: C6.2 IC3.12 Q2.2 | length 937.2
  Top Layer w50: 2015,5655 2175,5655 ; Q2.2 2185,5645 ; Q2.2@2195,5565 2195,5105 2215,5060 IC3.12@2380,4960
pads on no net: IC3.16 IC3.17 IC3.30 IC3.32 IC4.10

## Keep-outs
Keep-Out Layer:
  circle w20: c6347.36,4525 r130
  circle w20: c1574.96,4525 r130
  circle w10: c1965,2170 r50
  circle w10: c2335,2170 r50
  circle w10: c5670,2170 r50
  circle w10: c6035,2170 r50
  lines w10: 6205,1880 6210,1885
  lines w19.68: 1260,1880 1260,7084.96 ; 1260,7085 6622.95,7084.96 6622.95,1880 ; 1768.62,1485 6205,1485
  lines w20: 1260,1880 1770,1880 1770,1485 ; 2200,1255 2250,1305 ; 2580,1330 2600,1350 ; 5665,1325 5685,1345 ; 6205,1485 6205,1880 6625,1880
  text "Rys.8a Uklad sciezek sterownika - strona elementow" at 1400,1215 h120

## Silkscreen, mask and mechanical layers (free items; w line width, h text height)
Bottom Overlay:
  lines w10: 4000,1500 4000,1550 ; 4180,2820 4180,2770 4195,2770 4210,2770 4210,2820
  text "VCC" at 1480,5435 h30
  text "MISO" at 1815,5435 h30
  text "MOSI" at 1380,5335 h30
  text "SCK" at 1710,5310 h30 r270
  text "RST" at 1785,5225 h30
  text "GND" at 1455,5200 h30 r270
  text "W1" at 3775,4770 h60
  text "S4" at 1965,3215 h60 r270
  text "S3" at 2245,3210 h60 r270
  text "S2" at 2325,3210 h60 r270
  text "S1" at 2605,3210 h60 r270
  text "S6" at 2705,3210 h60 r270
  text "S5" at 2985,3205 h60 r270
Mechanical 4:
  lines w30: 2500,2345 2500,1980 1800,1980 1800,2350 2500,2350 ; 5495,1980 5495,2350 6195,2350 6195,1980 5495,1980
  lines w110: 1320,6095 1320,6965 ; 1325,6965 2235,6965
